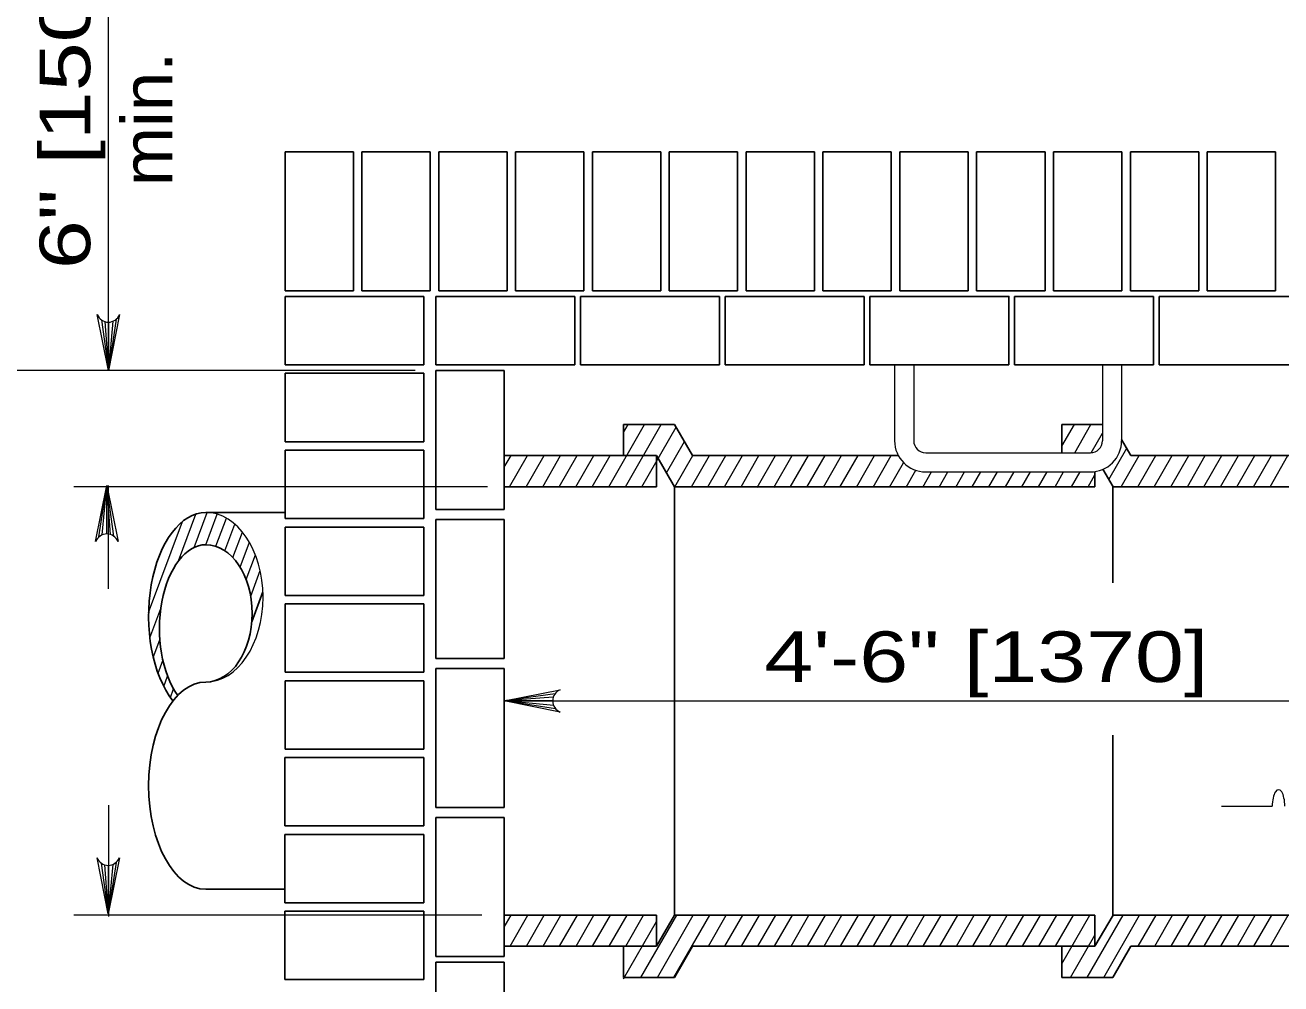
# Model space of a CAD drawing. Extents: x 750.7 to 784.7, y 860.1 to 882.1.
# Drawn here: x 766.797 to 770.769, y 870.48 to 873.513 of the extents above; entities that cross this region are included whole.
import ezdxf
from ezdxf.enums import TextEntityAlignment as Align

# ---------------------------------------------------------------- set-up
doc = ezdxf.new("R2010")
doc.units = 0
doc.header["$LTSCALE"] = 0.064
doc.layers.add('1', color=7, linetype='Continuous', lineweight=13)

msp = doc.modelspace()

# ---------------------------------------------------------------- linework, layer by layer
at = {"layer": '1'}
for p, q in [((767.06042, 872.42025), (767.06042, 873.72667)), ((767.038, 872.58058), (767.06042, 872.42025)), ((767.04908, 872.57517), (767.06042, 872.42025)), ((767.08517, 872.5825), (767.06042, 872.42025)), ((767.07483, 872.57633), (767.06042, 872.42025)), ((767.06042, 872.5735), (767.06042, 872.42025)), ((768.03025, 872.42025), (766.35725, 872.42025)), ((769.54708, 872.43842), (769.54708, 872.19817)), ((769.60767, 872.43842), (769.60767, 872.19817)), ((770.20458, 872.43842), (770.20458, 872.19817)), ((770.26517, 872.43842), (770.26517, 872.19817)), ((768.64317, 872.05283), (768.7565, 872.25)), ((768.68975, 872.22483), (768.70417, 872.25)), ((768.69542, 872.05283), (768.80875, 872.25)), ((770.07658, 872.1815), (770.11592, 872.25)), ((770.11675, 872.16033), (770.16825, 872.25)), ((768.74767, 872.05283), (768.85592, 872.24108)), ((770.169, 872.16033), (770.20458, 872.22225)), ((768.82542, 872.09708), (768.88217, 872.19583)), ((770.22483, 872.07558), (770.28158, 872.17433)), ((768.31267, 872.11467), (768.33383, 872.15142)), ((768.32942, 872.05283), (768.38608, 872.15142)), ((768.38167, 872.05283), (768.43842, 872.15142)), ((768.434, 872.05283), (768.49067, 872.15142)), ((768.48625, 872.05283), (768.54292, 872.15142)), ((768.53858, 872.05283), (768.59525, 872.15142)), ((768.59083, 872.05283), (768.6475, 872.15142)), ((768.85225, 872.05283), (768.90892, 872.15142)), ((768.90458, 872.05283), (768.96125, 872.15142)), ((768.95683, 872.05283), (769.0135, 872.15142)), ((769.00917, 872.05283), (769.06583, 872.15142)), ((769.06142, 872.05283), (769.11808, 872.15142)), ((769.11258, 872.05075), (769.17042, 872.15142)), ((769.16492, 872.05092), (769.22267, 872.15142)), ((769.21725, 872.051), (769.275, 872.15142)), ((769.26958, 872.05108), (769.32725, 872.15142)), ((769.32192, 872.05117), (769.37958, 872.15142)), ((769.37425, 872.05125), (769.43183, 872.15142)), ((769.42658, 872.05142), (769.48408, 872.15142)), ((769.479, 872.0515), (769.53642, 872.15142)), ((769.53133, 872.05158), (769.57567, 872.12875)), ((769.6455, 872.16033), (770.16675, 872.16033)), ((770.264, 872.05283), (770.32067, 872.15142)), ((770.31633, 872.05283), (770.373, 872.15142)), ((770.36858, 872.05283), (770.42525, 872.15142)), ((770.42092, 872.05283), (770.47758, 872.15142)), ((770.47317, 872.05283), (770.52983, 872.15142)), ((770.5255, 872.05283), (770.58217, 872.15142)), ((770.57775, 872.05283), (770.63442, 872.15142)), ((770.63, 872.05283), (770.68675, 872.15142)), ((770.68233, 872.05283), (770.739, 872.15142)), ((770.73458, 872.05283), (770.79133, 872.15142)), ((769.58367, 872.05167), (769.61417, 872.10483)), ((769.636, 872.05175), (769.66358, 872.09975)), ((769.6455, 872.09975), (770.16675, 872.09975)), ((769.68833, 872.05192), (769.71583, 872.09975)), ((769.74067, 872.052), (769.76817, 872.09975)), ((769.793, 872.05208), (769.82042, 872.09975)), ((769.84533, 872.05217), (769.87267, 872.09975)), ((769.89775, 872.05225), (769.925, 872.09975)), ((769.95008, 872.05233), (769.97725, 872.09975)), ((770.00242, 872.0525), (770.02958, 872.09975)), ((770.05475, 872.05258), (770.08183, 872.09975)), ((770.10708, 872.05267), (770.13417, 872.09975)), ((770.15942, 872.05275), (770.18092, 872.09008)), ((768.2595, 872.05283), (766.95058, 872.05283)), ((767.0305, 871.8945), (767.05533, 872.05667)), ((767.04092, 871.90067), (767.05533, 872.05667)), ((767.05533, 871.9035), (767.05533, 872.05667)), ((767.06667, 871.90183), (767.05533, 872.05667)), ((767.07775, 871.89642), (767.05533, 872.05667)), ((767.06042, 871.72975), (767.06042, 872.05667)), ((767.282, 871.81858), (767.33683, 871.96633)), ((767.3315, 871.861), (767.37242, 871.97133)), ((767.36842, 871.86958), (767.40417, 871.96617)), ((767.1875, 871.65467), (767.29425, 871.94258)), ((767.40025, 871.86442), (767.43333, 871.95367)), ((767.42875, 871.85042), (767.46, 871.93467)), ((767.45433, 871.8285), (767.48433, 871.90942)), ((767.477, 871.79858), (767.50625, 871.87742)), ((767.49617, 871.75942), (767.52525, 871.83767)), ((767.5105, 871.70708), (767.54042, 871.78767)), ((767.1915, 871.57442), (767.226, 871.66758)), ((767.20242, 871.51292), (767.22308, 871.56867)), ((767.2175, 871.46267), (767.23267, 871.50358)), ((767.23567, 871.42083), (767.24775, 871.45325)), ((767.2565, 871.386), (767.26658, 871.41308)), ((768.473, 871.39792), (768.31267, 871.3755)), ((768.46758, 871.38683), (768.31267, 871.3755)), ((768.31267, 871.3755), (769.42667, 871.3755)), ((768.46592, 871.3755), (768.31267, 871.3755)), ((768.46875, 871.36108), (768.31267, 871.3755)), ((768.47492, 871.35067), (768.31267, 871.3755)), ((769.42667, 871.3755), (771.49958, 871.3755)), ((767.06042, 871.04575), (767.06042, 870.69342)), ((770.5815, 871.042), (770.7415, 871.042)), ((767.03725, 870.86242), (767.05967, 870.70217)), ((767.04833, 870.857), (767.05967, 870.70217)), ((767.0845, 870.86433), (767.05967, 870.70217)), ((767.07408, 870.85817), (767.05967, 870.70217)), ((767.05967, 870.85533), (767.05967, 870.70217)), ((768.242, 870.69817), (766.95058, 870.69817)), ((768.31267, 870.65933), (768.33467, 870.6975)), ((768.33067, 870.59958), (768.38683, 870.69742)), ((768.38292, 870.59958), (768.43917, 870.6975)), ((768.43517, 870.59958), (768.49158, 870.69758)), ((768.4875, 870.59958), (768.54392, 870.69767)), ((768.53975, 870.59958), (768.59625, 870.69775)), ((768.59208, 870.59958), (768.64858, 870.69792)), ((768.64433, 870.59958), (768.70092, 870.698)), ((768.69667, 870.59958), (768.75325, 870.69808)), ((768.7445, 870.501), (768.85792, 870.69817)), ((768.79683, 870.501), (768.91017, 870.69817)), ((768.84908, 870.501), (768.9625, 870.69817)), ((768.95808, 870.59958), (769.01475, 870.69817)), ((769.01033, 870.59958), (769.067, 870.69817)), ((769.06267, 870.59958), (769.11933, 870.69817)), ((769.11492, 870.59958), (769.17158, 870.69817)), ((769.16725, 870.59958), (769.22392, 870.69817)), ((769.2195, 870.59958), (769.27617, 870.69817)), ((769.27183, 870.59958), (769.3285, 870.69817)), ((769.32408, 870.59958), (769.38075, 870.69817)), ((769.37633, 870.59958), (769.43308, 870.69817)), ((769.42867, 870.59958), (769.48533, 870.69817)), ((769.48092, 870.59958), (769.53758, 870.69817)), ((769.53325, 870.59958), (769.58992, 870.69817)), ((769.5855, 870.59958), (769.64217, 870.69817)), ((769.63783, 870.59958), (769.6945, 870.69817)), ((769.69008, 870.59958), (769.74675, 870.69817)), ((769.74242, 870.59958), (769.79908, 870.69817)), ((769.79467, 870.59958), (769.85133, 870.69817)), ((769.84692, 870.59958), (769.90367, 870.69817)), ((769.89925, 870.59958), (769.95592, 870.69817)), ((769.9515, 870.59958), (770.00817, 870.69817)), ((770.00383, 870.59958), (770.0605, 870.69817)), ((770.05608, 870.59958), (770.11275, 870.69817)), ((770.07658, 870.54425), (770.16508, 870.69817)), ((770.15625, 870.501), (770.26967, 870.69817)), ((770.20858, 870.501), (770.32192, 870.69817)), ((770.3175, 870.59958), (770.37425, 870.69817)), ((770.36983, 870.59958), (770.4265, 870.69817)), ((770.42208, 870.59958), (770.47875, 870.69817)), ((770.47442, 870.59958), (770.53108, 870.69817)), ((770.52667, 870.59958), (770.58333, 870.69817)), ((770.579, 870.59958), (770.63567, 870.69817)), ((770.63125, 870.59958), (770.68792, 870.69817)), ((770.68358, 870.59958), (770.74025, 870.69817)), ((770.73583, 870.59958), (770.7925, 870.69817)), ((768.68975, 870.49658), (768.794, 870.67792)), ((770.104, 870.501), (770.18092, 870.63475))]:
    msp.add_line(p, q, dxfattribs=at)
at = {"layer": '1', "lineweight": 25}
for p, q in [((767.61892, 872.67283), (767.61892, 873.11242)), ((767.61892, 873.11242), (767.83517, 873.11242)), ((767.83517, 872.67283), (767.83517, 873.11242)), ((767.862, 872.67283), (767.862, 873.11242)), ((767.862, 873.11242), (768.07825, 873.11242)), ((768.07825, 872.67283), (768.07825, 873.11242)), ((768.10508, 872.67283), (768.10508, 873.11242)), ((768.10508, 873.11242), (768.32133, 873.11242)), ((768.32133, 872.67283), (768.32133, 873.11242)), ((768.34817, 872.67283), (768.34817, 873.11242)), ((768.34817, 873.11242), (768.56442, 873.11242)), ((768.56442, 872.67283), (768.56442, 873.11242)), ((768.59125, 872.67283), (768.59125, 873.11242)), ((768.59125, 873.11242), (768.8075, 873.11242)), ((768.8075, 872.67283), (768.8075, 873.11242)), ((768.83433, 872.67283), (768.83433, 873.11242)), ((768.83433, 873.11242), (769.05058, 873.11242)), ((769.05058, 872.67283), (769.05058, 873.11242)), ((769.07742, 872.67283), (769.07742, 873.11242)), ((769.07742, 873.11242), (769.29367, 873.11242)), ((769.29367, 872.67283), (769.29367, 873.11242)), ((769.3205, 872.67283), (769.3205, 873.11242)), ((769.3205, 873.11242), (769.53675, 873.11242)), ((769.53675, 872.67283), (769.53675, 873.11242)), ((769.56358, 872.67283), (769.56358, 873.11242)), ((769.56358, 873.11242), (769.77983, 873.11242)), ((769.77983, 872.67283), (769.77983, 873.11242)), ((769.80667, 872.67283), (769.80667, 873.11242)), ((769.80667, 873.11242), (770.02292, 873.11242)), ((770.02292, 872.67283), (770.02292, 873.11242)), ((770.04975, 872.67283), (770.04975, 873.11242)), ((770.04975, 873.11242), (770.266, 873.11242)), ((770.266, 872.67283), (770.266, 873.11242)), ((770.29283, 873.11242), (770.50908, 873.11242)), ((770.29283, 872.67283), (770.29283, 873.11242)), ((770.50908, 872.67283), (770.50908, 873.11242)), ((770.53592, 873.11242), (770.75217, 873.11242)), ((770.53592, 872.67283), (770.53592, 873.11242)), ((770.75217, 872.67283), (770.75217, 873.11242)), ((767.61892, 872.67283), (767.83517, 872.67283)), ((768.05842, 872.65475), (767.61892, 872.65475)), ((767.61892, 872.43842), (767.61892, 872.65475)), ((767.862, 872.67283), (768.07825, 872.67283)), ((768.05842, 872.43842), (768.05842, 872.65475)), ((768.09642, 872.65475), (768.09642, 872.43842)), ((768.09642, 872.65475), (768.53592, 872.65467)), ((768.10508, 872.67283), (768.32133, 872.67283)), ((768.34817, 872.67283), (768.56442, 872.67283)), ((768.53592, 872.65467), (768.53592, 872.43842)), ((768.554, 872.65475), (768.554, 872.43842)), ((768.554, 872.65475), (768.99358, 872.65467)), ((768.59125, 872.67283), (768.8075, 872.67283)), ((768.83433, 872.67283), (769.05058, 872.67283)), ((768.99358, 872.65467), (768.99358, 872.43842)), ((769.01167, 872.65467), (769.45117, 872.65467)), ((769.01167, 872.65467), (769.01167, 872.43842)), ((769.07742, 872.67283), (769.29367, 872.67283)), ((769.3205, 872.67283), (769.53675, 872.67283)), ((769.45117, 872.65467), (769.45117, 872.43842)), ((769.46925, 872.65475), (769.46925, 872.43842)), ((769.56358, 872.67283), (769.77983, 872.67283)), ((769.80667, 872.67283), (770.02292, 872.67283)), ((769.92692, 872.65467), (769.92692, 872.43842)), ((769.92692, 872.65467), (770.36642, 872.65467)), ((770.04975, 872.67283), (770.266, 872.67283)), ((770.29283, 872.67283), (770.50908, 872.67283)), ((770.36642, 872.65467), (770.36642, 872.43842)), ((770.3845, 872.65475), (770.82408, 872.65467)), ((770.3845, 872.65467), (770.3845, 872.43842)), ((770.53592, 872.67283), (770.75217, 872.67283)), ((768.05842, 872.43842), (767.61892, 872.43842)), ((768.05842, 872.41158), (767.61892, 872.41158)), ((767.61892, 872.19533), (767.61892, 872.41158)), ((768.05842, 872.19533), (768.05842, 872.41158)), ((768.09642, 872.43842), (768.53592, 872.43842)), ((768.09642, 871.98075), (768.09642, 872.42025)), ((768.09642, 872.42025), (768.31267, 872.42025)), ((768.31267, 871.98075), (768.31267, 872.42025)), ((768.554, 872.43842), (768.99358, 872.43842)), ((769.01167, 872.43842), (769.45117, 872.43842)), ((769.46925, 872.43842), (769.90883, 872.43842)), ((769.92692, 872.43842), (770.36642, 872.43842)), ((770.3845, 872.43842), (770.82408, 872.43842)), ((768.85075, 872.25), (768.68975, 872.25)), ((768.68975, 872.15142), (768.68975, 872.25)), ((768.90792, 872.15142), (768.85075, 872.25)), ((770.20458, 872.25), (770.07658, 872.25)), ((770.07658, 872.16033), (770.07658, 872.25)), ((768.05842, 872.19533), (767.61892, 872.19533)), ((768.05842, 872.1685), (767.61892, 872.1685)), ((767.61892, 871.95225), (767.61892, 872.1685)), ((768.05842, 871.95225), (768.05842, 872.1685)), ((770.29483, 872.15142), (770.26517, 872.20258)), ((768.794, 872.15142), (768.31267, 872.15142)), ((768.85117, 872.05283), (768.794, 872.15142)), ((768.794, 872.05283), (768.794, 872.15142)), ((769.55883, 872.15142), (768.90792, 872.15142)), ((771.49958, 872.15142), (770.29483, 872.15142)), ((770.18092, 872.05283), (770.18092, 872.10075)), ((770.23808, 872.05283), (770.20608, 872.10792)), ((768.794, 872.05283), (768.31267, 872.05283)), ((768.85075, 870.69817), (768.85075, 872.05283)), ((770.18092, 872.05283), (768.85075, 872.05283)), ((770.23767, 871.74858), (770.23767, 872.05283)), ((771.49958, 872.05283), (770.23808, 872.05283)), ((767.61892, 871.97142), (767.3685, 871.97142)), ((768.09642, 871.98075), (768.31267, 871.98075)), ((768.05842, 871.95225), (767.61892, 871.95225)), ((768.09642, 871.50958), (768.09642, 871.94917)), ((768.09642, 871.94917), (768.31267, 871.94917)), ((768.31267, 871.50958), (768.31267, 871.94917)), ((768.05842, 871.92542), (767.61892, 871.92542)), ((767.61892, 871.70917), (767.61892, 871.92542)), ((768.05842, 871.70917), (768.05842, 871.92542)), ((767.51417, 871.62592), (767.54925, 871.7205)), ((768.05842, 871.70917), (767.61892, 871.70917)), ((768.05842, 871.68233), (767.61892, 871.68233)), ((767.61892, 871.46608), (767.61892, 871.68233)), ((768.05842, 871.46608), (768.05842, 871.68233)), ((768.09642, 871.50958), (768.31267, 871.50958)), ((768.05842, 871.46608), (767.61892, 871.46608)), ((768.09642, 871.0385), (768.09642, 871.47808)), ((768.09642, 871.47808), (768.31267, 871.47808)), ((768.31267, 871.0385), (768.31267, 871.47808)), ((768.05842, 871.43925), (767.61892, 871.43925)), ((767.61892, 871.223), (767.61892, 871.43925)), ((768.05842, 871.223), (768.05842, 871.43925)), ((770.23767, 870.69817), (770.23767, 871.26725)), ((768.05842, 871.223), (767.61892, 871.223)), ((768.05842, 871.19617), (767.61883, 871.19617)), ((767.61883, 870.97992), (767.61883, 871.19617)), ((768.05842, 870.97992), (768.05842, 871.19617)), ((768.09642, 871.0385), (768.31267, 871.0385)), ((768.05842, 870.97992), (767.61883, 870.97992)), ((768.09642, 870.56742), (768.09642, 871.00692)), ((768.09642, 871.00692), (768.31267, 871.00692)), ((768.31267, 870.56742), (768.31267, 871.00692)), ((768.05842, 870.95308), (767.61883, 870.95308)), ((767.61883, 870.73683), (767.61883, 870.95308)), ((768.05842, 870.73683), (768.05842, 870.95308)), ((767.61892, 870.77958), (767.3685, 870.77958)), ((768.05842, 870.73683), (767.61883, 870.73683)), ((768.05842, 870.71), (767.61883, 870.71)), ((767.61883, 870.49375), (767.61883, 870.71)), ((768.05842, 870.49375), (768.05842, 870.71)), ((768.794, 870.69817), (768.31267, 870.69817)), ((768.85117, 870.69817), (768.794, 870.59958)), ((768.794, 870.69817), (768.794, 870.59958)), ((770.18092, 870.69817), (768.85075, 870.69817)), ((770.23808, 870.69817), (770.18092, 870.59958)), ((770.18092, 870.69817), (770.18092, 870.59958)), ((771.49958, 870.69817), (770.23808, 870.69817)), ((768.794, 870.59958), (768.31267, 870.59958)), ((768.68975, 870.501), (768.68975, 870.59958)), ((768.90792, 870.59958), (768.85075, 870.501)), ((770.18092, 870.59958), (768.90792, 870.59958)), ((770.07658, 870.501), (770.07658, 870.59958)), ((770.29483, 870.59958), (770.23767, 870.501)), ((771.49958, 870.59958), (770.29483, 870.59958)), ((768.09642, 870.56742), (768.31267, 870.56742)), ((768.09642, 870.56742), (768.31267, 870.56742)), ((768.09642, 870.09625), (768.09642, 870.54925)), ((768.09642, 870.54925), (768.31267, 870.54925)), ((768.31267, 870.09625), (768.31267, 870.54925)), ((768.85075, 870.501), (768.68975, 870.501)), ((770.23767, 870.501), (770.07658, 870.501)), ((768.05842, 870.49375), (767.61883, 870.49375))]:
    msp.add_line(p, q, dxfattribs=at)
msp.add_lwpolyline([(769.46925, 872.65475), (769.90883, 872.65467), (769.90883, 872.43842)], dxfattribs=at)
at = {"layer": '1'}
for points in [[(767.09583, 872.59733), (767.06042, 872.42025), (767.025, 872.59733)], [(767.01992, 871.87958), (767.05533, 872.05667), (767.09075, 871.87958)], [(768.48975, 871.34008), (768.31267, 871.3755), (768.48975, 871.41092)], [(767.09508, 870.87925), (767.05967, 870.70217), (767.02425, 870.87925)]]:
    msp.add_lwpolyline(points, dxfattribs=at)
for centre, radius, start, end in [((767.06036, 872.61166), 0.03822, 202.08782, 337.91395), ((769.64547, 872.19813), 0.09841, 180.0002, 270.0001), ((769.64547, 872.19814), 0.03778, 180.00039, 270.00013), ((770.16678, 872.19814), 0.03778, 270.00019, 0.00039), ((770.16678, 872.19814), 0.09841, 270.00011, 0.0002), ((767.05536, 871.86531), 0.03822, 22.08782, 157.91395), ((768.50406, 871.37552), 0.03822, 112.08782, 247.91395), ((767.05964, 870.89351), 0.03822, 202.08782, 337.91395)]:
    msp.add_arc(centre, radius, start, end, dxfattribs=at)
at = {"layer": '1', "lineweight": 25}
for centre, major_axis, ratio, start_param, end_param in [((767.36851, 871.64364), (0, -0.32775), 0.552634, 3.1415914, 5.6706314), ((767.36851, 871.60405), (0, -0.26554), 0.552634, 3.1415935, 5.6320716), ((767.36851, 871.65233), (0, 0.21726), 0.675441, 3.1415927, 6.2831853), ((767.36851, 871.10732), (0, -0.32775), 0.552634, 3.1415927, 6.2831853)]:
    msp.add_ellipse(centre, major_axis=major_axis, ratio=ratio, start_param=start_param, end_param=end_param, dxfattribs=at)
at = {"layer": '1'}
for centre, major_axis, ratio, start_param, end_param in [((767.36851, 871.70324), (0, 0.26816), 0.675441, 3.1415927, 6.2831853), ((770.76152, 871.04199), (0, -0.05257), 0.380456, 1.5707963, 4.712389)]:
    msp.add_ellipse(centre, major_axis=major_axis, ratio=ratio, start_param=start_param, end_param=end_param, dxfattribs=at)

# ---------------------------------------------------------------- texts
for s, width, p in [('6" [150]', 1.3, (767.00267, 873.21583)), ('min.', 1.05, (767.26267, 873.21583))]:
    msp.add_text(s, height=0.16, rotation=90, dxfattribs=dict(at, width=width)).set_placement(p, align=Align.CENTER)
at = {"layer": '1', "width": 1.3}
msp.add_text('4\'-6" [1370]', height=0.16, dxfattribs=at).set_placement((769.13508, 871.43517))

doc.saveas('drawing.dxf')
